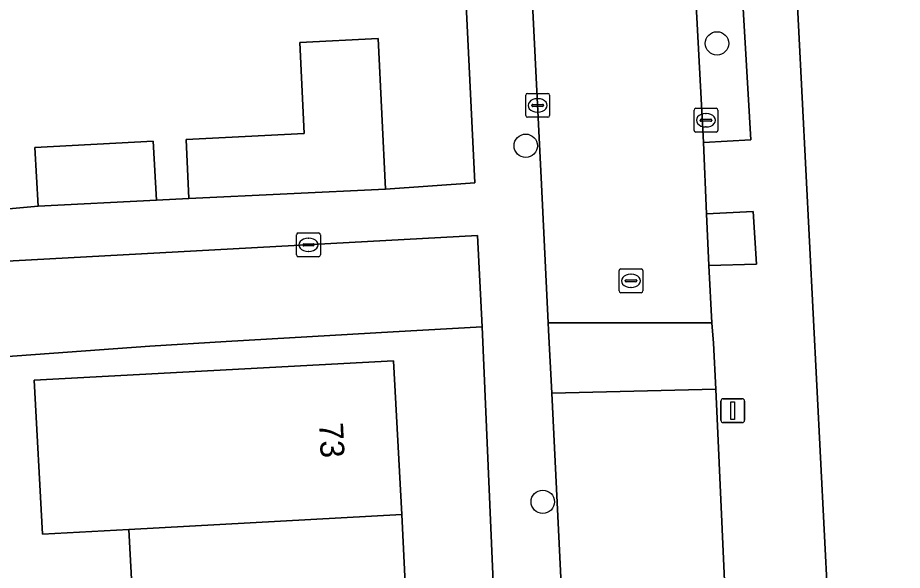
# Model space of a CAD drawing. Extents: x 161084 to 161928, y 385354 to 386522.
# Drawn here: x 161294.37 to 161331.43, y 386109.65 to 386132.82 of the extents above; entities that cross this region are included whole.
import ezdxf

# ---------------------------------------------------------------- set-up
doc = ezdxf.new("R2010")
doc.units = 0
for name, color, linetype in [('IMGEO_Boom', 7, 'Continuous'), ('IMGEO_Erf', 7, 'Continuous'), ('IMGEO_Groenvoorziening', 7, 'Continuous'), ('IMGEO_Kolk', 7, 'Continuous'), ('IMGEO_Lichtmast', 7, 'Continuous'), ('IMGEO_Muur', 7, 'Continuous'), ('IMGEO_Pand', 7, 'Continuous'), ('IMGEO_Pand_nummerreeks', 7, 'Continuous'), ('IMGEO_Rijbaan_lokaal_open', 7, 'Continuous'), ('IMGEO_Rioolput', 7, 'Continuous'), ('IMGEO_Voetpad_open', 7, 'Continuous')]:
    doc.layers.add(name, color=color, linetype=linetype)

msp = doc.modelspace()

# ---------------------------------------------------------------- linework, layer by layer
at = {"layer": 'IMGEO_Boom'}
for centre in [(161323.67, 386131.739), (161315.655, 386127.447), (161316.369, 386112.523)]:
    msp.add_circle(centre, 0.489, dxfattribs=at)
at = {"layer": 'IMGEO_Erf'}
for points in [[(161293.068, 386124.722), (161295.221, 386124.913), (161295.092, 386127.372), (161300.05, 386127.633), (161300.18, 386125.161), (161301.546, 386125.23), (161301.425, 386127.712), (161306.376, 386127.954), (161306.19, 386131.777), (161309.467, 386131.936), (161309.774, 386125.631), (161313.524, 386125.898), (161312.512, 386146.555)], [(161360.195, 386143.207), (161326.629, 386141.553), (161328.624, 386102.307), (161328.778, 386099.301), (161331.2, 386051.66), (161334.752, 386051.846)], [(161314.902, 386094.903), (161313.837, 386119.861), (161310.099, 386119.644), (161303.111, 386119.238), (161299.912, 386119.052), (161287.431, 386118.142), (161287.464, 386116.956), (161287.61, 386114.723), (161282.969, 386114.42), (161283.492, 386106.92)], [(161299.343, 386105.387), (161299.022, 386111.365), (161295.404, 386111.168), (161295.053, 386117.615), (161310.117, 386118.437), (161310.468, 386111.989), (161310.76, 386105.936)]]:
    msp.add_lwpolyline(points, dxfattribs=at)
at = {"layer": 'IMGEO_Groenvoorziening'}
for points in [[(161324.604, 386136.078), (161322.66, 386135.974), (161323.107, 386127.582), (161325.094, 386127.695)], [(161325.192, 386124.693), (161323.223, 386124.587), (161323.334, 386122.432), (161325.321, 386122.481)]]:
    msp.add_lwpolyline(points, close=True, dxfattribs=at)
at = {"layer": 'IMGEO_Kolk'}
for p, q in [((161315.655, 386128.713), (161315.655, 386129.565)), ((161315.73, 386129.639), (161316.582, 386129.639)), ((161316.143, 386129.419), (161316.168, 386129.419)), ((161316.656, 386129.565), (161316.656, 386128.713)), ((161315.914, 386129.133), (161315.914, 386129.145)), ((161316.352, 386129.096), (161315.954, 386129.096)), ((161315.957, 386129.182), (161316.355, 386129.182)), ((161316.398, 386129.145), (161316.398, 386129.133)), ((161322.707, 386128.09), (161322.707, 386128.942)), ((161322.782, 386129.016), (161323.634, 386129.016)), ((161323.708, 386128.942), (161323.708, 386128.09)), ((161316.582, 386128.639), (161315.73, 386128.639)), ((161316.166, 386128.859), (161316.141, 386128.859)), ((161323.195, 386128.796), (161323.22, 386128.796)), ((161322.966, 386128.51), (161322.966, 386128.522)), ((161323.404, 386128.473), (161323.006, 386128.473)), ((161323.009, 386128.559), (161323.407, 386128.559)), ((161323.218, 386128.236), (161323.193, 386128.236)), ((161323.45, 386128.522), (161323.45, 386128.51)), ((161323.634, 386128.016), (161322.782, 386128.016)), ((161306.128, 386123.794), (161306.98, 386123.794)), ((161306.053, 386122.868), (161306.053, 386123.72)), ((161306.541, 386123.574), (161306.566, 386123.574)), ((161307.054, 386123.72), (161307.054, 386122.868)), ((161306.312, 386123.288), (161306.312, 386123.3)), ((161306.75, 386123.251), (161306.352, 386123.251)), ((161306.355, 386123.337), (161306.753, 386123.337)), ((161306.564, 386123.014), (161306.539, 386123.014)), ((161306.796, 386123.3), (161306.796, 386123.288)), ((161306.98, 386122.794), (161306.128, 386122.794))]:
    msp.add_line(p, q, dxfattribs=at)
for points in [[(161315.655, 386128.713), (161315.655, 386129.565)], [(161315.73, 386129.639), (161316.582, 386129.639)], [(161316.656, 386129.565), (161316.656, 386128.713)], [(161322.707, 386128.09), (161322.707, 386128.942)], [(161322.782, 386129.016), (161323.634, 386129.016)], [(161323.708, 386128.942), (161323.708, 386128.09)], [(161316.582, 386128.639), (161315.73, 386128.639)], [(161323.634, 386128.016), (161322.782, 386128.016)], [(161306.128, 386123.794), (161306.98, 386123.794)], [(161306.053, 386122.868), (161306.053, 386123.72)], [(161307.054, 386123.72), (161307.054, 386122.868)], [(161306.98, 386122.794), (161306.128, 386122.794)]]:
    msp.add_lwpolyline(points, dxfattribs=at)
for centre, radius, start, end in [((161315.732, 386129.563), 0.0765, 91.552, 178.448), ((161315.732, 386129.563), 0.0765, 91.552, 178.448), ((161316.58, 386129.563), 0.0765, 1.552, 88.448), ((161316.58, 386129.563), 0.0765, 1.552, 88.448), ((161315.954, 386129.142), 0.0403, 85.8775, 175.7526), ((161315.951, 386129.132), 0.0366, 178.938, 274.7102), ((161316.355, 386129.139), 0.043, 264.8664, 352.4533), ((161316.359, 386129.144), 0.0386, 1.7309, 96.639), ((161322.784, 386128.94), 0.0765, 91.552, 178.448), ((161322.784, 386128.94), 0.0765, 91.552, 178.448), ((161323.632, 386128.94), 0.0765, 1.552, 88.448), ((161323.632, 386128.94), 0.0765, 1.552, 88.448), ((161315.732, 386128.715), 0.0765, 181.552, 268.448), ((161315.732, 386128.715), 0.0765, 181.552, 268.448), ((161316.58, 386128.715), 0.0765, 271.552, 358.448), ((161316.58, 386128.715), 0.0765, 271.552, 358.448), ((161323.006, 386128.519), 0.0403, 85.8775, 175.7526), ((161323.003, 386128.509), 0.0366, 178.938, 274.7102), ((161323.407, 386128.516), 0.043, 264.8664, 352.4533), ((161323.411, 386128.521), 0.0386, 1.7309, 96.639), ((161322.784, 386128.092), 0.0765, 181.552, 268.448), ((161322.784, 386128.092), 0.0765, 181.552, 268.448), ((161323.632, 386128.092), 0.0765, 271.552, 358.448), ((161323.632, 386128.092), 0.0765, 271.552, 358.448), ((161306.13, 386123.718), 0.0765, 91.552, 178.448), ((161306.13, 386123.718), 0.0765, 91.552, 178.448), ((161306.978, 386123.718), 0.0765, 1.552, 88.448), ((161306.978, 386123.718), 0.0765, 1.552, 88.448), ((161306.352, 386123.297), 0.0403, 85.8775, 175.7526), ((161306.349, 386123.287), 0.0366, 178.938, 274.7102), ((161306.753, 386123.294), 0.043, 264.8664, 352.4533), ((161306.757, 386123.299), 0.0386, 1.7309, 96.639), ((161306.13, 386122.87), 0.0765, 181.552, 268.448), ((161306.13, 386122.87), 0.0765, 181.552, 268.448), ((161306.978, 386122.87), 0.0765, 271.552, 358.448), ((161306.978, 386122.87), 0.0765, 271.552, 358.448)]:
    msp.add_arc(centre, radius, start, end, dxfattribs=at)
for centre, major_axis, ratio, start_param, end_param in [((161316.142, 386129.139), (-0.387, 0.002), 0.722429, 4.712389, 7.853982), ((161316.167, 386129.139), (-0.39, 0.002), 0.717154, 1.570796, 4.712389), ((161323.194, 386128.516), (-0.387, 0.002), 0.722429, 4.712389, 7.853982), ((161323.219, 386128.516), (-0.39, 0.002), 0.717154, 1.570796, 4.712389), ((161306.54, 386123.294), (-0.387, 0.002), 0.722429, 4.712389, 7.853982), ((161306.565, 386123.294), (-0.39, 0.002), 0.717154, 1.570796, 4.712389)]:
    msp.add_ellipse(centre, major_axis=major_axis, ratio=ratio, start_param=start_param, end_param=end_param, dxfattribs=at)
at = {"layer": 'IMGEO_Lichtmast'}
for p, q in [((161323.835, 386115.944), (161323.835, 386116.744)), ((161323.835, 386116.744), (161323.835, 386115.944)), ((161323.935, 386116.844), (161324.725, 386116.844)), ((161324.725, 386116.844), (161323.935, 386116.844)), ((161324.825, 386116.744), (161324.825, 386115.944)), ((161324.825, 386115.944), (161324.825, 386116.744)), ((161324.725, 386115.844), (161323.935, 386115.844)), ((161323.935, 386115.844), (161324.725, 386115.844))]:
    msp.add_line(p, q, dxfattribs=at)
msp.add_lwpolyline([(161324.255, 386116.719), (161324.405, 386116.719), (161324.405, 386115.969), (161324.255, 386115.969), (161324.255, 386116.719)], dxfattribs=at)
for centre, start, end in [((161323.935, 386116.744), 90, 180), ((161323.935, 386116.744), 90, 180), ((161324.725, 386116.744), 0, 90), ((161324.725, 386116.744), 360, 90), ((161323.935, 386115.944), 180, 270), ((161323.935, 386115.944), 180, 270), ((161324.725, 386115.944), 270, 0), ((161324.725, 386115.944), 270, 0)]:
    msp.add_arc(centre, 0.1, start, end, dxfattribs=at)
at = {"layer": 'IMGEO_Muur'}
msp.add_lwpolyline([(161303.111, 386119.238), (161310.099, 386119.644)], dxfattribs=at)
at = {"layer": 'IMGEO_Pand'}
for points in [[(161309.774, 386125.631), (161309.467, 386131.936), (161306.19, 386131.777), (161306.376, 386127.954), (161301.425, 386127.712), (161301.546, 386125.23)], [(161300.18, 386125.161), (161300.05, 386127.633), (161295.092, 386127.372), (161295.221, 386124.913)], [(161299.022, 386111.365), (161310.468, 386111.989), (161310.117, 386118.437), (161295.053, 386117.615), (161295.404, 386111.168)], [(161299.022, 386111.365), (161299.343, 386105.387), (161310.76, 386105.936), (161310.468, 386111.989)]]:
    msp.add_lwpolyline(points, close=True, dxfattribs=at)
at = {"layer": 'IMGEO_Rijbaan_lokaal_open'}
for points in [[(161315.248, 386147.415), (161316.313, 386125.821), (161316.6, 386120.02), (161323.457, 386120.025), (161323.334, 386122.432), (161323.223, 386124.587), (161323.107, 386127.582), (161322.66, 386135.974), (161322.511, 386138.373)], [(161283.492, 386106.92), (161282.969, 386114.42), (161282.823, 386116.653), (161287.464, 386116.956), (161287.431, 386118.142), (161299.912, 386119.052), (161303.111, 386119.238), (161310.099, 386119.644), (161313.837, 386119.861), (161313.636, 386123.679), (161276.243, 386121.64), (161276.198, 386122.457), (161269.834, 386121.972), (161267.916, 386121.9), (161268.171, 386119.94), (161272.22, 386120.502), (161272.778, 386116.48), (161273.124, 386113.984), (161273.603, 386110.526), (161274.429, 386104.558)], [(161324.581, 386098.161), (161324.201, 386105.596), (161324.022, 386108.291), (161323.621, 386117.24), (161316.746, 386117.07), (161317.522, 386101.325), (161319.318, 386067.515), (161319.68, 386060.686), (161319.946, 386055.681), (161320.201, 386050.813), (161320.3, 386048.876), (161320.272, 386048.078)]]:
    msp.add_lwpolyline(points, dxfattribs=at)
msp.add_lwpolyline([(161323.528, 386119.169), (161323.457, 386120.025), (161316.6, 386120.02), (161316.614, 386119.719), (161316.746, 386117.07), (161323.621, 386117.24)], close=True, dxfattribs=at)
at = {"layer": 'IMGEO_Rioolput'}
for p, q in [((161319.64, 386122.286), (161320.492, 386122.286)), ((161319.565, 386121.36), (161319.565, 386122.212)), ((161320.053, 386122.066), (161320.078, 386122.066)), ((161320.566, 386122.212), (161320.566, 386121.36)), ((161319.824, 386121.78), (161319.824, 386121.792)), ((161320.262, 386121.743), (161319.864, 386121.743)), ((161319.867, 386121.829), (161320.265, 386121.829)), ((161320.308, 386121.792), (161320.308, 386121.78)), ((161320.492, 386121.286), (161319.64, 386121.286)), ((161320.076, 386121.506), (161320.051, 386121.506))]:
    msp.add_line(p, q, dxfattribs=at)
for points in [[(161319.64, 386122.286), (161320.492, 386122.286)], [(161319.565, 386121.36), (161319.565, 386122.212)], [(161320.566, 386122.212), (161320.566, 386121.36)], [(161320.492, 386121.286), (161319.64, 386121.286)]]:
    msp.add_lwpolyline(points, dxfattribs=at)
for centre, radius, start, end in [((161319.642, 386122.21), 0.0765, 91.552, 178.448), ((161319.642, 386122.21), 0.0765, 91.552, 178.448), ((161320.49, 386122.21), 0.0765, 1.552, 88.448), ((161320.49, 386122.21), 0.0765, 1.552, 88.448), ((161319.864, 386121.789), 0.0403, 85.8775, 175.7526), ((161319.861, 386121.779), 0.0366, 178.938, 274.7102), ((161320.265, 386121.786), 0.043, 264.8664, 352.4533), ((161320.269, 386121.791), 0.0386, 1.7309, 96.639), ((161319.642, 386121.362), 0.0765, 181.552, 268.448), ((161319.642, 386121.362), 0.0765, 181.552, 268.448), ((161320.49, 386121.362), 0.0765, 271.552, 358.448), ((161320.49, 386121.362), 0.0765, 271.552, 358.448)]:
    msp.add_arc(centre, radius, start, end, dxfattribs=at)
for centre, major_axis, ratio, start_param, end_param in [((161320.052, 386121.786), (-0.387, 0.002), 0.722429, 4.712389, 7.853982), ((161320.077, 386121.786), (-0.39, 0.002), 0.717154, 1.570796, 4.712389)]:
    msp.add_ellipse(centre, major_axis=major_axis, ratio=ratio, start_param=start_param, end_param=end_param, dxfattribs=at)
at = {"layer": 'IMGEO_Voetpad_open'}
for points in [[(161320.272, 386048.078), (161320.3, 386048.876), (161320.201, 386050.813), (161319.946, 386055.681), (161319.68, 386060.686), (161319.318, 386067.515), (161317.522, 386101.325), (161316.746, 386117.07), (161316.614, 386119.719), (161316.6, 386120.02), (161316.313, 386125.821), (161315.248, 386147.415)], [(161312.512, 386146.555), (161313.524, 386125.898), (161309.774, 386125.631), (161301.546, 386125.23), (161300.18, 386125.161), (161295.221, 386124.913), (161293.068, 386124.722), (161288.15, 386124.431), (161283.132, 386124.134), (161281.027, 386124.139), (161276.096, 386123.801), (161276.198, 386122.457), (161276.243, 386121.64), (161313.636, 386123.679), (161313.837, 386119.861), (161314.902, 386094.903), (161317.411, 386044.073), (161321.23, 386044.898), (161322.406, 386044.972)], [(161322.098, 386146.508), (161322.2, 386144.068), (161324.127, 386144.171), (161324.449, 386138.477), (161322.511, 386138.373), (161322.66, 386135.974), (161324.604, 386136.078), (161325.094, 386127.695), (161323.107, 386127.582), (161323.223, 386124.587), (161325.192, 386124.693), (161325.321, 386122.481), (161323.334, 386122.432), (161323.457, 386120.025), (161323.528, 386119.169), (161323.621, 386117.24), (161324.022, 386108.291)], [(161328.778, 386099.301), (161328.624, 386102.307), (161326.629, 386141.553), (161326.491, 386144.261), (161326.427, 386145.537), (161326.373, 386146.591)]]:
    msp.add_lwpolyline(points, dxfattribs=at)

# ---------------------------------------------------------------- texts
at = {"layer": 'IMGEO_Pand_nummerreeks'}
msp.add_text('73', height=1, rotation=272.7614, dxfattribs=at).set_placement((161306.999, 386115.825))

doc.saveas('drawing.dxf')
